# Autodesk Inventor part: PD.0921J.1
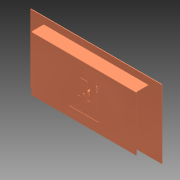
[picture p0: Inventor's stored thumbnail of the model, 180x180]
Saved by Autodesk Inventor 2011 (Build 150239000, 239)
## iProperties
Created: 2014-06
Part Number: PD.0921J.1
Document SubType Name: Modeling
Designer: Evgeny
Density: 1 g/cm^3
Author: Evgeny
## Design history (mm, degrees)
sketch "Эскиз1"
  geometry: L1 (-81, 42.5)-(81, 42.5); L2 (81, 42.5)-(81, -42.5); L3 (81, -42.5)-(-81, -42.5); L4 (-81, -42.5)-(-81, 42.5); L5 (23, 27.5)-(23, -27.5); L6 (23, -27.5)-(-23, -27.5); L7 (-23, -27.5)-(-23, 27.5); L8 (19, 27.5)-(19, -23.5); L9 (19, -23.5)-(-19, -23.5); L10 (-19, -23.5)-(-19, 27.5); L11 (-23, 27.5)-(-19, 27.5); L12 (19, 27.5)-(23, 27.5); L13 (-9.5, 22.5)-(9.5, 22.5); L14 (9.5, 22.5)-(9.5, -6.5); L15 (-9.5, -6.5)-(-9.5, 22.5); L16 (-5.5, -6.5)-(-5.5, 18.5); L17 (-5.5, 18.5)-(5.5, 18.5); L18 (5.5, 18.5)-(5.5, -6.5); L19 (9.5, -6.5)-(5.5, -6.5); L20 (-5.5, -6.5)-(-9.5, -6.5); C1 r 3.4 at (0, -3); 1 further point
  constraints: 40 end point, 10 parallel, 4 horizontal, 4 perpendicular, 2 collinear, 1 centre point
  dimensions: "d0" = 85 distance between parallel lines of L3 L1; "d1" = 162 distance between parallel lines of L2 L4; "d2" = 81 distance from line of L4 point (0, 0); "d3" = 42.5 distance from line of L3 point (0, 0); "d4" = 4 distance between parallel lines of L10 L7; "d5" = 4 distance between parallel lines of L5 L8; "d6" = 4 distance between parallel lines of L6 L9; "d7" = 55 distance between parallel lines of L12 L6; "d8" = 27.5 distance from line of point (0, 0) L6; "d9" = 46 distance between parallel lines of L5 L7; "d10" = 23 distance from line of L7 point (0, 0); "d11" = 4 distance between parallel lines of L16 L15; "d12" = 4 distance between parallel lines of L18 L14; "d13" = 4 distance between parallel lines of L13 L17; "d14" = 29 distance between parallel lines of L13 L20; "d15" = 19 distance between parallel lines of L14 L15; "d16" = 9.5 distance from line of point (0, 0) L15; "d19" = 6.8 diameter of C1; "d20" = 45.5 distance from line of L1 C1.centre; "d43" = 49 distance between parallel lines of L1 L20
extrude "Выдавливание2" new body sketch "Эскиз1" distance "d21" = 0.5; taper "d22" = 0 deg
extrude "Выдавливание3" join sketch "Эскиз1" distance "d23" = 1.5; taper "d25" = 0 deg; dims "d24" = 19.5, "d26" = 0
sketch "Эскиз2"
  geometry: L1 (81, -42.5)-(81, 42.5) reference; L2 (-81, 42.5)-(81, 42.5); L3 (81, 42.5)-(81, 42); L4 (81, 42)-(-81, 42); L5 (-81, 42)-(-81, 42.5); 1 further point
  constraints: 8 end point, 2 parallel, 1 horizontal, 1 perpendicular, 1 point on line
  dimensions: "d27" = 0.5 distance between parallel lines of L4 L2
extrude "Выдавливание4" join sketch "Эскиз2" distance "d28" = 18.5; taper "d29" = 0 deg
fillet "Сопряжение1" dims "d30" = 1.5
fillet "Сопряжение2" dims "d31" = 1
sketch "Эскиз3"
  geometry: L1 (-81, 42.5)-(81, 42.5) reference; L2 (-101.5, 53)-(101.5, 53); L3 (101.5, 53)-(101.5, -53); L4 (101.5, -53)-(-101.5, -53); L5 (-101.5, -53)-(-101.5, 53); C1 r 4.5 at (0, -3); 2 further points
  constraints: 8 end point, 2 parallel, 1 centre point, 1 horizontal, 1 perpendicular
  dimensions: "d32" = 9 diameter of C1; "d33" = 56 distance from line of L2 C1.centre; "d34" = 106 distance between parallel lines of L4 L2; "d35" = 203 distance between parallel lines of L3 L5; "d36" = 101.5 distance from line of L5 C1.centre; "d37" = 20.5 distance from line of L5 point (-81, 42); "d38" = 10.5 distance between parallel lines of L2 L1
extrude "Выдавливание6" join sketch "Эскиз3" distance "d41" = 1; taper "d42" = 0 deg
node "Твердое тело2"
